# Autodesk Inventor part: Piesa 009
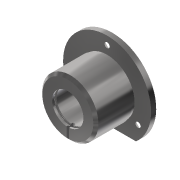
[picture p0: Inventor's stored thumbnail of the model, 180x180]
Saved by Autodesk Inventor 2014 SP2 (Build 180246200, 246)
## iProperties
Created: 2009-01
Part Number: Piesa 009
Document SubType Name: Modeling
Designer: Costel
Material: Steel
Density: 7.85 g/cm^3
Appearance: Steel - Polished
Author: Costel
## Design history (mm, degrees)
sketch "Sketch1"
  geometry: L1 (12.25, 0)-(20, 0); L2 (22, 2)-(22, 28.3); L3 (10.025, 0)-(41.175, 0) reference; L4 (12.25, 34.8)-(34.5, 34.8); L5 (34.5, 34.8)-(34.5, 30.8); L6 (34.5, 30.8)-(22, 30.8); L7 (0, -3.48)-(0, 45.24) reference; L8 (22, 28.3)-(21.5, 28.3); L9 (21.5, 28.3)-(21.5, 30.8); L10 (21.5, 30.8)-(22, 30.8); L11 (20, 0)-(22, 2); L12 (12.25, 34.8)-(12.25, 33.3); L13 (12.25, 31.3)-(12.25, 3.5); L14 (12.25, 1.5)-(12.25, 0); A1 r 1 centre (12.25, 2.5) between (12.25, 1.5) and (12.25, 3.5); A2 r 1 centre (12.25, 32.3) between (12.25, 31.3) and (12.25, 33.3); 1 further point
  constraints: 24 end point, 7 perpendicular, 4 point on circle, 3 point on line, 2 centre point, 2 horizontal, 2 parallel, 1 collinear, 1 equal radius
  dimensions: "d0" = 34.8 distance between parallel lines of L1 L4; "d1" = 4 distance of L4.end L5.end; "d2" = 69 diameter of L5 L7; "d3" = 44 diameter of L2 L7; "d5" = 2.5 distance of L8.end L9.end; "d6" = 43 diameter of L9 L7; "d7" = 2 distance of L1.end point (22, 0); "d8" = 2 distance of L2.start point (22, 0) (= d7); "d9" = 1 radius of A1; "d10" = 2.5 distance from line of L1 A1.centre; "d11" = 2.5 distance from line of L4 A2.centre
revolve "Revolution1" sketch "Sketch1" stored, may be unused: angle "d12" = 90 deg
sketch "Sketch2"
  geometry: L1 (0, -41.4)-(0, 55.2) reference; L2 (-1, -10.537)-(1, -10.537); L3 (1, -10.537)-(1, -23.732); L4 (1, -23.732)-(-1, -23.732); L5 (-1, -23.732)-(-1, -10.537)
  constraints: 8 end point, 2 parallel, 1 horizontal, 1 perpendicular, 1 other
  dimensions: "d13" = 2 distance of L3.end L4.end
extrude "Extrusion1" cut sketch "Sketch2" distance "d14" = 5; taper "d15" = 0 deg
sketch "Sketch3"
  geometry: L1 (-28.377, -26)-(25.146, -26); L2 (25.146, -26)-(25.146, -44.023); L3 (25.146, -44.023)-(-28.377, -44.023); L4 (-28.377, -44.023)-(-28.377, -26); L5 (-41.4, 0)-(55.2, 0) reference
  constraints: 8 end point, 2 parallel, 1 horizontal, 1 perpendicular
  dimensions: "d16" = 26 distance between parallel lines of L5 L1
extrude "Extrusion2" cut sketch "Sketch3" stored distance "d17" = 5; taper "d18" = 0 deg
sketch "Sketch4" dims "d19" = 56
  geometry: L1 (0, 32.05)-(0, -52.65) reference; C1 r 12.25 at (0, 0) reference; 2 further points
  constraints: 1 coincident, 1 point on line, 1 vertical alignment, 2 other
hole "Hole1" sketch "Sketch4" at (0, -28) diameter "d20" = 3; stored, may be unused: countersink angle "d24" = 90 deg, drill point angle "d26" = 118 deg; dims "d21" = 6, "d22" = 12, "d23" = 2, "d25" = 8
pattern_circular "Circular Pattern1" dims angle "d28" = 360 deg
body "Solid1"
other parameters: "d4" = 24.5
